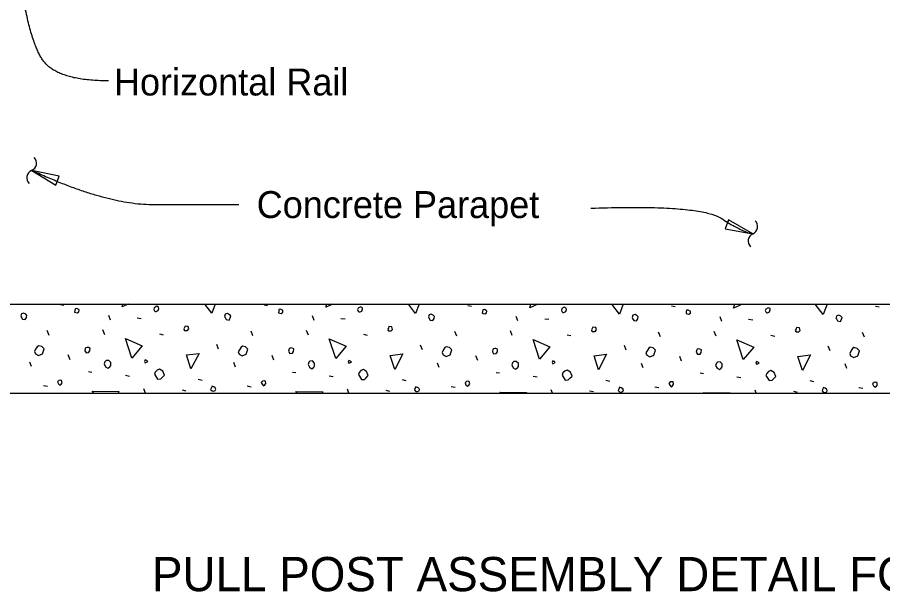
# Model space of a CAD drawing. Extents: x 110698 to 110915, y 110390 to 110472.
# Drawn here: x 110780.09 to 110786.56, y 110409.37 to 110413.66 of the extents above; entities that cross this region are included whole.
import ezdxf

# ---------------------------------------------------------------- set-up
doc = ezdxf.new("R2010")
doc.units = 0
for name, color, linetype in [('Border', 7, 'Continuous'), ('PlotBorder_dp', 7, 'Continuous'), ('SheetBorder_dp', 7, 'Continuous'), ('SheetLines_dp', 7, 'Continuous')]:
    doc.layers.add(name, color=color, linetype=linetype)

msp = doc.modelspace()

# ---------------------------------------------------------------- linework, layer by layer
at = {"layer": 'PlotBorder_dp'}
for points in [[(110780.1961, 110412.5176), (110780.377, 110412.4085), (110780.4028, 110412.4742)], [(110785.5883, 110412.0439), (110785.4048, 110412.1483), (110785.3806, 110412.082)]]:
    msp.add_lwpolyline(points, close=True, dxfattribs=at)
for centre, start, end in [((110780.1727, 110412.5716), 292.70915, 44.43637), ((110780.2187, 110412.4616), 112.70915, 224.43637), ((110785.5641, 110412.0988), 294.14658, 45.87379), ((110785.6129, 110411.99), 114.14657, 225.87379)]:
    msp.add_arc(centre, 0.0596, start, end, dxfattribs=at)
for points in [[(110780.7702, 110413.1874), (110780.3723, 110413.1874), (110780.1683, 110413.5244), (110780.1071, 110413.9813)], [(110781.7461, 110412.2604), (110781.4531, 110412.2604), (110780.7536, 110412.2604), (110780.1959, 110412.5173)], [(110784.3776, 110412.2353), (110785.1905, 110412.2637), (110785.5119, 110412.0555), (110785.5886, 110412.0443)]]:
    msp.add_open_spline(points, degree=2, dxfattribs=at)
at = {"layer": 'SheetBorder_dp'}
for p, q in [((110780.4096, 110411.5159), (110780.4361, 110411.5106)), ((110781.9334, 110411.5124), (110781.9599, 110411.5071)), ((110783.4572, 110411.5088), (110783.4837, 110411.5035)), ((110784.981, 110411.5053), (110785.0075, 110411.5)), ((110786.5048, 110411.5018), (110786.5314, 110411.4965)), ((110780.7843, 110411.3992), (110780.772, 110411.4328)), ((110780.9841, 110411.4151), (110781.0159, 110411.4116)), ((110782.3082, 110411.3957), (110782.2958, 110411.4293)), ((110782.5079, 110411.4116), (110782.5397, 110411.4081)), ((110783.832, 110411.3922), (110783.8196, 110411.4257)), ((110784.0317, 110411.4081), (110784.0636, 110411.4045)), ((110785.3558, 110411.3886), (110785.3434, 110411.4222)), ((110785.5555, 110411.4045), (110785.5874, 110411.401)), ((110780.3265, 110411.2843), (110780.3123, 110411.3197)), ((110780.7419, 110411.2896), (110780.7278, 110411.325)), ((110781.152, 110411.2967), (110781.1803, 110411.2896)), ((110781.8503, 110411.2808), (110781.8362, 110411.3161)), ((110782.2657, 110411.2861), (110782.2516, 110411.3214)), ((110782.6759, 110411.2932), (110782.7041, 110411.2861)), ((110783.3741, 110411.2773), (110783.36, 110411.3126)), ((110783.7895, 110411.2826), (110783.7754, 110411.3179)), ((110784.1997, 110411.2896), (110784.228, 110411.2826)), ((110784.8979, 110411.2737), (110784.8838, 110411.3091)), ((110785.3134, 110411.279), (110785.2992, 110411.3144)), ((110785.7235, 110411.2861), (110785.7518, 110411.279)), ((110786.4218, 110411.2702), (110786.4076, 110411.3055)), ((110781.594, 110411.18), (110781.5798, 110411.2154)), ((110783.1178, 110411.1765), (110783.1037, 110411.2118)), ((110784.6416, 110411.173), (110784.6275, 110411.2083)), ((110786.1654, 110411.1694), (110786.1513, 110411.2048)), ((110780.4838, 110411.1022), (110780.4697, 110411.1376)), ((110782.0076, 110411.0987), (110781.9935, 110411.1341)), ((110780.1957, 110411.051), (110780.1833, 110411.0846)), ((110781.7195, 110411.0474), (110781.7071, 110411.081)), ((110783.2433, 110411.0439), (110783.2309, 110411.0775)), ((110783.5315, 110411.0952), (110783.5173, 110411.1305)), ((110784.7671, 110411.0404), (110784.7547, 110411.074)), ((110785.0553, 110411.0916), (110785.0411, 110411.127)), ((110786.2909, 110411.0368), (110786.2786, 110411.0704)), ((110780.6217, 110411.0139), (110780.6465, 110411.0103)), ((110782.1455, 110411.0103), (110782.1703, 110411.0068)), ((110783.6693, 110411.0068), (110783.6941, 110411.0032)), ((110785.1932, 110411.0032), (110785.2179, 110410.9997)), ((110780.8975, 110410.9856), (110780.9275, 110410.9803)), ((110781.442, 110410.9573), (110781.4702, 110410.9502)), ((110782.4213, 110410.982), (110782.4513, 110410.9767)), ((110782.9658, 110410.9537), (110782.9941, 110410.9467)), ((110783.9451, 110410.9785), (110783.9752, 110410.9732)), ((110784.4896, 110410.9502), (110784.5179, 110410.9431)), ((110785.4689, 110410.975), (110785.499, 110410.9697)), ((110786.0134, 110410.9467), (110786.0417, 110410.9396)), ((110780.2841, 110410.9096), (110780.3141, 110410.9043)), ((110781.046, 110410.8512), (110781.0336, 110410.8848)), ((110781.32, 110410.8777), (110781.3483, 110410.8707)), ((110781.8079, 110410.906), (110781.8379, 110410.9007)), ((110782.5685, 110410.8512), (110782.5574, 110410.8813)), ((110782.8438, 110410.8742), (110782.8721, 110410.8671)), ((110783.3317, 110410.9025), (110783.3617, 110410.8972)), ((110784.091, 110410.8512), (110784.0812, 110410.8777)), ((110784.8555, 110410.8989), (110784.8856, 110410.8936)), ((110785.6135, 110410.8512), (110785.605, 110410.8742)), ((110786.3793, 110410.8954), (110786.4094, 110410.8901)), ((110784.3676, 110410.8707), (110784.3959, 110410.8636)), ((110785.8914, 110410.8671), (110785.9197, 110410.8601))]:
    msp.add_line(p, q, dxfattribs=at)
for points in [[(110780.5174, 110411.4576), (110780.5369, 110411.4523), (110780.5492, 110411.4611), (110780.551, 110411.4735), (110780.5475, 110411.477), (110780.5333, 110411.4841), (110780.5209, 110411.4823), (110780.5192, 110411.4699), (110780.5174, 110411.4576)], [(110780.8727, 110411.4982), (110780.8788, 110411.5179)], [(110780.9165, 110411.5179), (110780.8727, 110411.4982)], [(110781.1202, 110411.4629), (110781.1273, 110411.4629), (110781.1414, 110411.4699), (110781.1467, 110411.4858), (110781.145, 110411.4947), (110781.1308, 110411.5018), (110781.1131, 110411.4911), (110781.1096, 110411.4805), (110781.1131, 110411.4699), (110781.1202, 110411.4629)], [(110781.5427, 110411.4505), (110781.4915, 110411.5179)], [(110781.5679, 110411.5179), (110781.5427, 110411.4505)], [(110782.0412, 110411.454), (110782.0607, 110411.4487), (110782.073, 110411.4576), (110782.0748, 110411.4699), (110782.0713, 110411.4735), (110782.0571, 110411.4805), (110782.0448, 110411.4788), (110782.043, 110411.4664), (110782.0412, 110411.454)], [(110782.3965, 110411.4947), (110782.4037, 110411.5179)], [(110782.4482, 110411.5179), (110782.3965, 110411.4947)], [(110782.644, 110411.4593), (110782.6511, 110411.4593), (110782.6652, 110411.4664), (110782.6706, 110411.4823), (110782.6688, 110411.4911), (110782.6546, 110411.4982), (110782.637, 110411.4876), (110782.6334, 110411.477), (110782.637, 110411.4664), (110782.644, 110411.4593)], [(110783.0665, 110411.447), (110783.0126, 110411.5179)], [(110783.093, 110411.5179), (110783.0665, 110411.447)], [(110783.565, 110411.4505), (110783.5845, 110411.4452), (110783.5969, 110411.454), (110783.5986, 110411.4664), (110783.5951, 110411.4699), (110783.581, 110411.477), (110783.5686, 110411.4752), (110783.5668, 110411.4629), (110783.565, 110411.4505)], [(110783.9204, 110411.4911), (110783.9286, 110411.5179)], [(110783.9799, 110411.5179), (110783.9204, 110411.4911)], [(110784.1678, 110411.4558), (110784.1749, 110411.4558), (110784.1891, 110411.4629), (110784.1944, 110411.4788), (110784.1926, 110411.4876), (110784.1785, 110411.4947), (110784.1608, 110411.4841), (110784.1572, 110411.4735), (110784.1608, 110411.4629), (110784.1678, 110411.4558)], [(110784.5903, 110411.4434), (110784.5338, 110411.5179)], [(110784.6182, 110411.5179), (110784.5903, 110411.4434)], [(110785.0889, 110411.447), (110785.1083, 110411.4417), (110785.1207, 110411.4505), (110785.1224, 110411.4629), (110785.1189, 110411.4664), (110785.1048, 110411.4735), (110785.0924, 110411.4717), (110785.0906, 110411.4593), (110785.0889, 110411.447)], [(110785.4442, 110411.4876), (110785.4535, 110411.5179)], [(110785.5116, 110411.5179), (110785.4442, 110411.4876)], [(110785.6917, 110411.4523), (110785.6987, 110411.4523), (110785.7129, 110411.4593), (110785.7182, 110411.4752), (110785.7164, 110411.4841), (110785.7023, 110411.4911), (110785.6846, 110411.4805), (110785.6811, 110411.4699), (110785.6846, 110411.4593), (110785.6917, 110411.4523)], [(110786.1142, 110411.4399), (110786.0549, 110411.5179)], [(110786.1433, 110411.5179), (110786.1142, 110411.4399)], [(110780.1179, 110411.4222), (110780.1267, 110411.4063), (110780.1479, 110411.4028), (110780.1568, 110411.4187), (110780.1603, 110411.4328), (110780.1515, 110411.4417), (110780.1356, 110411.4505), (110780.1197, 110411.4452), (110780.1144, 110411.4293), (110780.1179, 110411.4222)], [(110781.6417, 110411.4187), (110781.6505, 110411.4028), (110781.6718, 110411.3992), (110781.6806, 110411.4151), (110781.6841, 110411.4293), (110781.6753, 110411.4381), (110781.6594, 110411.447), (110781.6435, 110411.4417), (110781.6382, 110411.4257), (110781.6417, 110411.4187)], [(110783.1655, 110411.4151), (110783.1744, 110411.3992), (110783.1956, 110411.3957), (110783.2044, 110411.4116), (110783.208, 110411.4257), (110783.1991, 110411.4346), (110783.1832, 110411.4434), (110783.1673, 110411.4381), (110783.162, 110411.4222), (110783.1655, 110411.4151)], [(110784.6893, 110411.4116), (110784.6982, 110411.3957), (110784.7194, 110411.3922), (110784.7282, 110411.4081), (110784.7318, 110411.4222), (110784.7229, 110411.431), (110784.707, 110411.4399), (110784.6911, 110411.4346), (110784.6858, 110411.4187), (110784.6893, 110411.4116)], [(110786.2132, 110411.4081), (110786.222, 110411.3922), (110786.2432, 110411.3886), (110786.252, 110411.4045), (110786.2556, 110411.4187), (110786.2467, 110411.4275), (110786.2308, 110411.4363), (110786.2149, 110411.431), (110786.2096, 110411.4151), (110786.2132, 110411.4081)], [(110781.3394, 110411.3214), (110781.3606, 110411.3214), (110781.3712, 110411.3321), (110781.3659, 110411.3515), (110781.343, 110411.3533), (110781.3394, 110411.3427), (110781.3341, 110411.3338), (110781.3394, 110411.3214), (110781.3359, 110411.325)], [(110782.8632, 110411.3179), (110782.8845, 110411.3179), (110782.8951, 110411.3285), (110782.8898, 110411.348), (110782.8668, 110411.3497), (110782.8632, 110411.3391), (110782.8579, 110411.3303), (110782.8632, 110411.3179), (110782.8597, 110411.3214)], [(110784.3871, 110411.3144), (110784.4083, 110411.3144), (110784.4189, 110411.325), (110784.4136, 110411.3444), (110784.3906, 110411.3462), (110784.3871, 110411.3356), (110784.3817, 110411.3267), (110784.3871, 110411.3144), (110784.3835, 110411.3179)], [(110785.9109, 110411.3108), (110785.9321, 110411.3108), (110785.9427, 110411.3214), (110785.9374, 110411.3409), (110785.9144, 110411.3427), (110785.9109, 110411.3321), (110785.9056, 110411.3232), (110785.9109, 110411.3108), (110785.9073, 110411.3144)], [(110780.9452, 110411.1146), (110780.8975, 110411.2613), (110781.023, 110411.2065), (110780.9452, 110411.1146)], [(110780.224, 110411.1464), (110780.2469, 110411.1341), (110780.277, 110411.1464), (110780.2894, 110411.1836), (110780.2717, 110411.2012), (110780.2487, 110411.2065), (110780.2381, 110411.1995), (110780.2257, 110411.18), (110780.2169, 110411.1641), (110780.224, 110411.1464)], [(110781.7478, 110411.1429), (110781.7708, 110411.1305), (110781.8008, 110411.1429), (110781.8132, 110411.18), (110781.7955, 110411.1977), (110781.7725, 110411.203), (110781.7619, 110411.1959), (110781.7495, 110411.1765), (110781.7407, 110411.1606), (110781.7478, 110411.1429)], [(110782.469, 110411.1111), (110782.4213, 110411.2578), (110782.5468, 110411.203), (110782.469, 110411.1111)], [(110783.2716, 110411.1394), (110783.2946, 110411.127), (110783.3246, 110411.1394), (110783.337, 110411.1765), (110783.3193, 110411.1942), (110783.2963, 110411.1995), (110783.2857, 110411.1924), (110783.2734, 110411.173), (110783.2645, 110411.157), (110783.2716, 110411.1394)], [(110783.9928, 110411.1075), (110783.9451, 110411.2543), (110784.0706, 110411.1995), (110783.9928, 110411.1075)], [(110785.5167, 110411.104), (110785.4689, 110411.2507), (110785.5944, 110411.1959), (110785.5167, 110411.104)], [(110780.5934, 110411.1694), (110780.6023, 110411.1535), (110780.6217, 110411.1553), (110780.6305, 110411.1676), (110780.6323, 110411.1871), (110780.6199, 110411.1924), (110780.6111, 110411.1942), (110780.6005, 110411.1906), (110780.597, 110411.1871), (110780.5934, 110411.1694)], [(110781.3872, 110411.0333), (110781.3536, 110411.1376), (110781.4473, 110411.15), (110781.3872, 110411.0333)], [(110782.1172, 110411.1659), (110782.1261, 110411.15), (110782.1455, 110411.1517), (110782.1544, 110411.1641), (110782.1561, 110411.1836), (110782.1438, 110411.1889), (110782.1349, 110411.1906), (110782.1243, 110411.1871), (110782.1208, 110411.1836), (110782.1172, 110411.1659)], [(110782.911, 110411.0298), (110782.8774, 110411.1341), (110782.9711, 110411.1464), (110782.911, 110411.0298)], [(110783.6411, 110411.1623), (110783.6499, 110411.1464), (110783.6693, 110411.1482), (110783.6782, 110411.1606), (110783.6799, 110411.18), (110783.6676, 110411.1853), (110783.6587, 110411.1871), (110783.6481, 110411.1836), (110783.6446, 110411.18), (110783.6411, 110411.1623)], [(110784.4348, 110411.0262), (110784.4012, 110411.1305), (110784.4949, 110411.1429), (110784.4348, 110411.0262)], [(110784.7954, 110411.1358), (110784.8184, 110411.1235), (110784.8484, 110411.1358), (110784.8608, 110411.173), (110784.8431, 110411.1906), (110784.8202, 110411.1959), (110784.8095, 110411.1889), (110784.7972, 110411.1694), (110784.7883, 110411.1535), (110784.7954, 110411.1358)], [(110785.1649, 110411.1588), (110785.1737, 110411.1429), (110785.1932, 110411.1447), (110785.202, 110411.157), (110785.2038, 110411.1765), (110785.1914, 110411.1818), (110785.1825, 110411.1836), (110785.1719, 110411.18), (110785.1684, 110411.1765), (110785.1649, 110411.1588)], [(110785.9586, 110411.0227), (110785.925, 110411.127), (110786.0187, 110411.1394), (110785.9586, 110411.0227)], [(110786.3192, 110411.1323), (110786.3422, 110411.1199), (110786.3723, 110411.1323), (110786.3846, 110411.1694), (110786.367, 110411.1871), (110786.344, 110411.1924), (110786.3334, 110411.1853), (110786.321, 110411.1659), (110786.3122, 110411.15), (110786.3192, 110411.1323)], [(110780.7384, 110411.0704), (110780.749, 110411.0492), (110780.7667, 110411.0386), (110780.7808, 110411.0492), (110780.7879, 110411.0598), (110780.7879, 110411.081), (110780.772, 110411.0969), (110780.7525, 110411.0952), (110780.7437, 110411.0863), (110780.7384, 110411.0704)], [(110781.0442, 110411.0793), (110781.0637, 110411.0881), (110781.0566, 110411.0952), (110781.0442, 110411.1005), (110781.0389, 110411.0881), (110781.0442, 110411.0793)], [(110782.2622, 110411.0669), (110782.2728, 110411.0457), (110782.2905, 110411.0351), (110782.3046, 110411.0457), (110782.3117, 110411.0563), (110782.3117, 110411.0775), (110782.2958, 110411.0934), (110782.2763, 110411.0916), (110782.2675, 110411.0828), (110782.2622, 110411.0669)], [(110782.568, 110411.0757), (110782.5875, 110411.0846), (110782.5804, 110411.0916), (110782.568, 110411.0969), (110782.5627, 110411.0846), (110782.568, 110411.0757)], [(110783.786, 110411.0634), (110783.7966, 110411.0421), (110783.8143, 110411.0315), (110783.8284, 110411.0421), (110783.8355, 110411.0527), (110783.8355, 110411.074), (110783.8196, 110411.0899), (110783.8002, 110411.0881), (110783.7913, 110411.0793), (110783.786, 110411.0634)], [(110784.0918, 110411.0722), (110784.1113, 110411.081), (110784.1042, 110411.0881), (110784.0918, 110411.0934), (110784.0865, 110411.081), (110784.0918, 110411.0722)], [(110785.3098, 110411.0598), (110785.3204, 110411.0386), (110785.3381, 110411.028), (110785.3523, 110411.0386), (110785.3593, 110411.0492), (110785.3593, 110411.0704), (110785.3434, 110411.0863), (110785.324, 110411.0846), (110785.3151, 110411.0757), (110785.3098, 110411.0598)], [(110785.6157, 110411.0687), (110785.6351, 110411.0775), (110785.628, 110411.0846), (110785.6157, 110411.0899), (110785.6103, 110411.0775), (110785.6157, 110411.0687)], [(110781.1149, 110410.9944), (110781.1379, 110410.9573), (110781.1609, 110410.9591), (110781.1697, 110410.9679), (110781.1892, 110410.9873), (110781.1768, 110411.0174), (110781.152, 110411.0315), (110781.1344, 110411.0245), (110781.1202, 110411.0103), (110781.1149, 110410.9944)], [(110782.6387, 110410.9909), (110782.6617, 110410.9537), (110782.6847, 110410.9555), (110782.6935, 110410.9644), (110782.713, 110410.9838), (110782.7006, 110411.0139), (110782.6759, 110411.028), (110782.6582, 110411.0209), (110782.644, 110411.0068), (110782.6387, 110410.9909)], [(110784.1625, 110410.9873), (110784.1855, 110410.9502), (110784.2085, 110410.952), (110784.2173, 110410.9608), (110784.2368, 110410.9803), (110784.2244, 110411.0103), (110784.1997, 110411.0245), (110784.182, 110411.0174), (110784.1678, 110411.0032), (110784.1625, 110410.9873)], [(110785.6864, 110410.9838), (110785.7093, 110410.9467), (110785.7323, 110410.9484), (110785.7412, 110410.9573), (110785.7606, 110410.9767), (110785.7482, 110411.0068), (110785.7235, 110411.0209), (110785.7058, 110411.0139), (110785.6917, 110410.9997), (110785.6864, 110410.9838)], [(110780.3954, 110410.9219), (110780.406, 110410.9113), (110780.4166, 110410.9184), (110780.4237, 110410.929), (110780.4202, 110410.9467), (110780.4113, 110410.9484), (110780.399, 110410.9467), (110780.3884, 110410.9361), (110780.3954, 110410.9219)], [(110781.9193, 110410.9184), (110781.9299, 110410.9078), (110781.9405, 110410.9149), (110781.9475, 110410.9255), (110781.944, 110410.9431), (110781.9352, 110410.9449), (110781.9228, 110410.9431), (110781.9122, 110410.9325), (110781.9193, 110410.9184)], [(110783.4431, 110410.9149), (110783.4537, 110410.9043), (110783.4643, 110410.9113), (110783.4713, 110410.9219), (110783.4678, 110410.9396), (110783.459, 110410.9414), (110783.4466, 110410.9396), (110783.436, 110410.929), (110783.4431, 110410.9149)], [(110784.9669, 110410.9113), (110784.9775, 110410.9007), (110784.9881, 110410.9078), (110784.9952, 110410.9184), (110784.9916, 110410.9361), (110784.9828, 110410.9378), (110784.9704, 110410.9361), (110784.9598, 110410.9255), (110784.9669, 110410.9113)], [(110781.5445, 110410.8689), (110781.5569, 110410.8671), (110781.5692, 110410.8724), (110781.5728, 110410.883), (110781.5675, 110410.8919), (110781.5569, 110410.8989), (110781.5445, 110410.9043), (110781.5374, 110410.8901), (110781.5339, 110410.8795), (110781.5445, 110410.8689)], [(110783.0683, 110410.8654), (110783.0807, 110410.8636), (110783.093, 110410.8689), (110783.0966, 110410.8795), (110783.0913, 110410.8883), (110783.0807, 110410.8954), (110783.0683, 110410.9007), (110783.0612, 110410.8866), (110783.0577, 110410.876), (110783.0683, 110410.8654)], [(110784.5921, 110410.8618), (110784.6045, 110410.8601), (110784.6169, 110410.8654), (110784.6204, 110410.876), (110784.6151, 110410.8848), (110784.6045, 110410.8919), (110784.5921, 110410.8972), (110784.585, 110410.883), (110784.5815, 110410.8724), (110784.5921, 110410.8618)], [(110786.1159, 110410.8583), (110786.1283, 110410.8565), (110786.1407, 110410.8618), (110786.1442, 110410.8724), (110786.1389, 110410.8813), (110786.1283, 110410.8883), (110786.1159, 110410.8936), (110786.1089, 110410.8795), (110786.1053, 110410.8689), (110786.1159, 110410.8583)], [(110786.4907, 110410.9078), (110786.5013, 110410.8972), (110786.5119, 110410.9043), (110786.519, 110410.9149), (110786.5154, 110410.9325), (110786.5066, 110410.9343), (110786.4942, 110410.9325), (110786.4836, 110410.9219), (110786.4907, 110410.9078)], [(110780.6603, 110410.8512), (110780.6482, 110410.8671), (110780.848, 110410.8654), (110780.8427, 110410.8512)], [(110782.1814, 110410.8512), (110782.172, 110410.8636), (110782.3718, 110410.8618), (110782.3678, 110410.8512)], [(110783.7026, 110410.8512), (110783.6959, 110410.8601), (110783.8956, 110410.8583), (110783.893, 110410.8512)], [(110785.2237, 110410.8512), (110785.2197, 110410.8565), (110785.4194, 110410.8548), (110785.4181, 110410.8512)]]:
    msp.add_lwpolyline(points, dxfattribs=at)
at = {"layer": 'SheetLines_dp'}
for p, q in [((110775.4386, 110411.5179), (110798.2125, 110411.5179)), ((110775.4386, 110410.8512), (110798.2125, 110410.8512))]:
    msp.add_line(p, q, dxfattribs=at)

# ---------------------------------------------------------------- texts
at = {"layer": 'Border'}
for s, height, p in [('Horizontal Rail', 0.2016, (110780.8112, 110413.0782)), ('Concrete Parapet', 0.2016, (110781.8783, 110412.1616)), ('PULL POST ASSEMBLY DETAIL FOR CONCRETE PARAPETS', 0.256001, (110781.0954, 110409.3712))]:
    msp.add_text(s, height=height, dxfattribs=at).set_placement(p)

doc.saveas('drawing.dxf')
